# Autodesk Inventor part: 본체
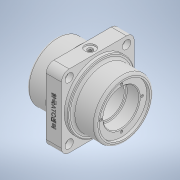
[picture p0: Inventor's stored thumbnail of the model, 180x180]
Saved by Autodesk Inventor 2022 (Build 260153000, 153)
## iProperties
Created: 2023-10
Part Number: 본체
Material: 일반
Document SubType Name: Modeling
Designer: PC-13
Density: 1 g/cm^3
Appearance: 기본값
Mass: 353.914 g
Surface Area: 541.824 cm^2
Volume: 353.914 cm^3
Author: PC-13
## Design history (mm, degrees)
sketch "스케치2"
  geometry: L1 (47.5, 47.5)-(-47.5, 47.5); L2 (-47.5, 47.5)-(-47.5, -47.5); L3 (-47.5, -47.5)-(47.5, -47.5); L4 (47.5, -47.5)-(47.5, 47.5); L5 (47.5, 47.5)-(-47.5, -47.5); L6 (-47.5, 47.5)-(47.5, -47.5); 1 further point
  constraints: 12 end point, 2 midpoint, 2 parallel, 1 horizontal, 1 perpendicular
  dimensions: "d2" = 95 distance between parallel lines of L2 L4; "d3" = 95 distance between parallel lines of L1 L3
extrude "돌출1" new body sketch "스케치2" stored distance "d4" = 20; taper "d5" = 0 deg
sketch "스케치3"
  geometry: C1 r 44 at (0, 0); 1 further point
  constraints: 1 centre point, 1 coincident
  dimensions: "d6" = 88 diameter of C1
extrude "돌출2" join sketch "스케치3" distance "d7" = 5; taper "d8" = 0 deg
sketch "스케치4"
  geometry: C1 r 38 at (0, 0); 1 further point
  constraints: 1 centre point, 1 coincident
  dimensions: "d9" = 76 diameter of C1
extrude "돌출3" join sketch "스케치4" distance "d10" = 30; taper "d11" = 0 deg
fillet "모깎기1" dims "d12" = 10
sketch "스케치6"
  geometry: C1 r 53 at (0, 0); A1 r 10 centre (-37.5, 37.5) between (-37.5, 47.5) and (-47.5, 37.5) reference; A2 r 10 centre (37.5, 37.5) between (47.5, 37.5) and (37.5, 47.5) reference; A3 r 10 centre (37.5, -37.5) between (37.5, -47.5) and (47.5, -37.5) reference; A4 r 10 centre (-37.5, -37.5) between (-47.5, -37.5) and (-37.5, -47.5) reference; 5 further points
  constraints: 5 coincident, 1 centre point
  dimensions: "d13" = 106 diameter of C1
hole "구멍1" sketch "스케치6" at (-37.5, 37.5), (37.5, 37.5), (37.5, -37.5), (-37.5, -37.5) diameter "d14" = 6.6; stored, may be unused: countersink angle "d18" = 90 deg, drill point angle "d20" = 118 deg; dims "d15" = 22, "d16" = 11, "d17" = 7, "d19" = 8
sketch "스케치7"
  geometry: C1 r 3.3 at (-37.5, -37.5) reference; C2 r 3.3 at (-37.5, 37.5) reference; C3 r 3.3 at (37.5, 37.5) reference; C4 r 3.3 at (37.5, -37.5) reference; C5 r 5.5 at (-37.5, -37.5); C6 r 5.5 at (-37.5, 37.5); C7 r 5.5 at (37.5, 37.5); C8 r 5.5 at (37.5, -37.5); 1 further point
  constraints: 4 centre point, 4 coincident
  dimensions: "d21" = 11 diameter of C5; "d22" = 11 diameter of C6; "d23" = 11 diameter of C7; "d24" = 11 diameter of C8
extrude "돌출4" cut sketch "스케치7" distance "d25" = 7; taper "d26" = 0 deg
chamfer "모따기1" distance "d27" = 1; stored, may be unused: second distance "d28" = 2, angle "d29" = 45 deg
fillet "모깎기2" dims "d30" = 3
fillet "모깎기3" dims "d31" = 3
sketch "스케치9"
  geometry: C1 r 33 at (0, 0); 1 further point
  constraints: 1 centre point, 1 coincident
  dimensions: "d32" = 66 diameter of C1
extrude "돌출5" cut sketch "스케치9" distance "d33" = 4; taper "d34" = 0 deg
sketch "스케치10"
  geometry: C1 r 23.5 at (0, 0); 1 further point
  constraints: 1 centre point, 1 coincident
  dimensions: "d35" = 47 diameter of C1
extrude "돌출6" cut sketch "스케치10" distance "d36" = 17; taper "d37" = 0 deg
sketch "스케치11"
  geometry: A1 r 27 centre (0, 0) between (0, 27) and (27, 0); 3 further points
  constraints: 4 point on circle, 2 horizontal alignment, 2 vertical alignment, 1 centre point, 1 coincident
  dimensions: "d38" = 54 diameter of A1
hole "구멍2" sketch "스케치11" at (0, 27), (27, 0), (0, -27), (-27, 0) diameter "d39" = 3.242; stored, may be unused: countersink angle "d43" = 90 deg, drill point angle "d45" = 118 deg; dims "d40" = 8, "d41" = 11, "d42" = 7, "d44" = 10
sketch "스케치12"
  geometry: L1 (0, 0)-(0, 75) reference; 2 further points
  constraints: 1 coincident, 1 other
  dimensions: "d46" = 10 distance from line of L1 point (10, 37.5)
extrude "돌출7" join sketch "스케치12" distance "d47" = 0.5; taper "d48" = 0 deg
sketch "스케치14"
  geometry: C1 r 7 at (10, -37.5); 1 further point
  constraints: 1 centre point, 1 coincident
  dimensions: "d49" = 14 diameter of C1
extrude "돌출8" cut sketch "스케치14" distance "d50" = 2; taper "d51" = 0 deg
sketch "스케치15"
  geometry: C1 r 7 at (0, 0) reference; 2 further points
  constraints: 1 coincident
hole "구멍3" sketch "스케치15" at (0, 0) diameter "d52" = 5.1881; stored, may be unused: countersink angle "d56" = 90 deg, drill point angle "d58" = 118 deg; dims "d53" = 14, "d54" = 7, "d55" = 2, "d57" = 30
sketch "스케치16"
  geometry: C1 r 20.5 at (0, 0); 1 further point
  constraints: 1 centre point, 1 coincident
  dimensions: "d59" = 41 diameter of C1
extrude "돌출9" cut sketch "스케치16" distance "d60" = 50; taper "d61" = 0 deg
chamfer "모따기2" distance "d62" = 1; stored, may be unused: second distance "d63" = 2, angle "d64" = 45 deg
fillet "모깎기4" dims "d65" = 1
node "솔리드1"
mirror "미러1"
node "작업 평면1"
feature "A9D066F2-1C7D-4E18-AEED-F7BC21143FA4" dims "d14" = 6.6, "d15" = 22, "d16" = 11, "d17" = 7, "d18" = 90 deg, "d19" = 8, "d20" = 118 deg
